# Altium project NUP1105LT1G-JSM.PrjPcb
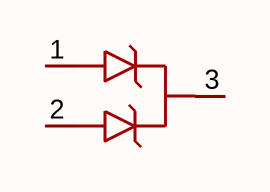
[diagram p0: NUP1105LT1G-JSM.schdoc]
1 sheet, 1 parts. Net scope: global (net labels, ports and power ports of the same name join across sheets).

## Sheet NUP1105LT1G-JSM.schdoc
size 127 x 101 mm

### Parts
D?  nup1105lt1g-jsm  [SOT-23-3_L2.9-W1.3-P1.90-LS2.4-BR]  (value not drawn)

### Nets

Not connected (* = marked no-connect by the designer): D? 1 2 3

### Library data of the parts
D? = nup1105lt1g-jsm: 极性:双向;反向截止电压(Vrwm):24V;钳位电压:44V;峰值脉冲电流(Ipp):8A@8/20us;峰值脉冲功率(Ppp):350W@8/20us;击穿电压(VBR):32V;; Manufacturer: JSMSEMI(杰盛微); AddInBom: yes; ModelId: c62791f0466c4ae2a892c056b845b0ca; ModelName: SOT-23-3P_L2.9-W1.3-H1.0-LS2.4-P0.95; ModelTransform: 98.425,114.173,0,180,0,0,0.0005,-0.0005,0; Polarity: 双向; Reverse Stand-Off Voltage (Vrwm): 24V; Clamping Voltage: 44V; Voltage - Breakdown: 32V; Reverse Leakage Current (Ir): 100nA; Number of Channels: 双路; level of protection: IEC 61000-4-4；IEC 61000-4-5；IEC 61000-4-2; Type: TVS; Junction Capacitance: 30pF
